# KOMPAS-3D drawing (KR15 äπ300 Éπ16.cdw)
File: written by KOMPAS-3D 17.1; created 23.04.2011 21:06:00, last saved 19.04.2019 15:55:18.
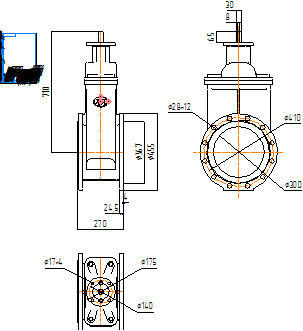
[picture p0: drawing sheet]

Sheet 1: A4, portrait

Title block, sheet 1: name: KR15 Ду300 Ру16; material: Внимание! Данный продукт является объектом авторского права ООО «Торговый Дом АДЛ». / Запрещается изменение, копирование, распространение / (в том числе путем копирования на другие сайты и ресурсы в Интернете) / или любое иное использование информации и объектов без предварительного / согласия правообладателя (ООО «Торговый Дом АДЛ»).; scale: 1:1; sheets: 1; organisation: ООО "Торговый дом АДЛ"; sheet format: A4; stored path: \\adlc.lan\data\АДЛ_ПКД\3D-модели\ADL production\Клиновые задвижки серии KR ГРАНАР\Клиновые задвижки KR15\С голым штоком\KOMPAS 2D\KR15 Ду300 Ру16.cdw

Views: Спереди 4, Проекционный вид 5
Dimensions and other numbers on the sheet: 710; 270; 24,5; 4; 367; 455; 175; 17; 140; 1:1; 1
